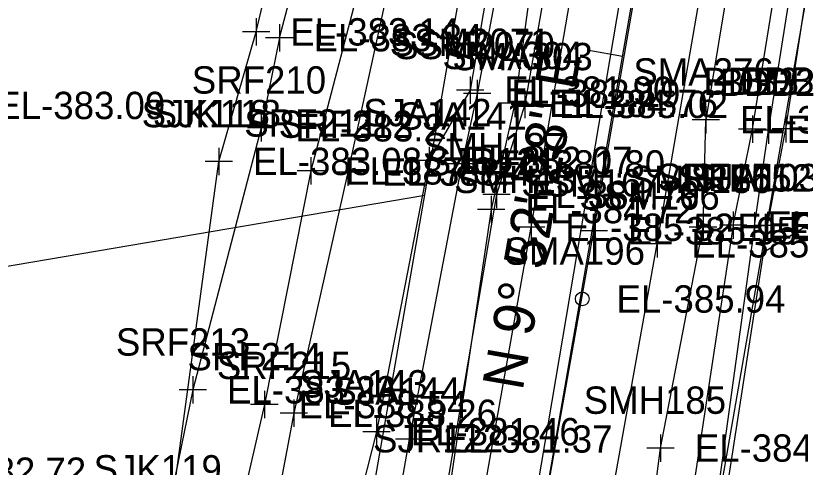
# Model space of a CAD drawing. Extents: x 1189978 to 1314812, y 571533 to 629339.
# Drawn here: x 1217630 to 1217744.7, y 622456.3 to 622522.3 of the extents above; entities that cross this region are included whole.
import ezdxf

# ---------------------------------------------------------------- set-up
doc = ezdxf.new("R2010")
doc.units = 0
for name, color, linetype in [('SURVEY - CENTERLINE - Preliminary', 7, 'Continuous'), ('SURVEY - CENTERLINE - Preliminary Text', 7, 'Continuous'), ('SURVEY - DRAINAGE - Area Shapes', 7, 'Continuous'), ('SURVEY - DTM - Breaklines', 7, 'Continuous'), ('SURVEY - DTM - Breaklines - Points - Elevations', 7, 'Continuous'), ('SURVEY - DTM - Breaklines - Points - Locators', 7, 'Continuous'), ('SURVEY - DTM - Breaklines - Points - Numbers', 7, 'Continuous'), ('SURVEY - DTM - Spot Points - Elevations', 7, 'Continuous'), ('SURVEY - DTM - Spot Points - Locators', 7, 'Continuous'), ('SURVEY - DTM - Spot Points - Point Numbers', 7, 'Continuous'), ('SURVEY - PROPERTY - ROW Lines', 7, 'Continuous'), ('SURVEY - PROPERTY - ROW Lines Text', 7, 'Continuous'), ('SURVEY - TRANSPORTATION - Roads', 7, 'Continuous'), ('SURVEY - TRANSPORTATION - Roads - Points - Elevations', 7, 'Continuous'), ('SURVEY - TRANSPORTATION - Roads - Points - Locators', 7, 'Continuous'), ('SURVEY - TRANSPORTATION - Roads - Points - Numbers', 7, 'Continuous'), ('SURVEY - VEGETATION - Features - Points - Elevations', 7, 'Continuous'), ('SURVEY - VEGETATION - Features - Points - Locators', 7, 'Continuous'), ('SURVEY - VEGETATION - Features - Points - Numbers', 7, 'Continuous'), ('SURVEY - VEGETATION - Features with Text', 7, 'Continuous')]:
    doc.layers.add(name, color=color, linetype=linetype)

msp = doc.modelspace()

# ---------------------------------------------------------------- linework, layer by layer
at = {"layer": 'SURVEY - CENTERLINE - Preliminary'}
msp.add_line((1217671.49, 622245.09), (1217757.38, 622738.49), dxfattribs=at)
msp.add_line((1217671.49, 622245.09), (1217757.38, 622738.49), dxfattribs=at)
at = {"layer": 'SURVEY - CENTERLINE - Preliminary Text'}
msp.add_line((1217718.71, 622516.35), (1217713.78, 622517.2), dxfattribs=at)
at = {"layer": 'SURVEY - DRAINAGE - Area Shapes'}
msp.add_line((1217415.87, 620731.68), (1218149.36, 625079.9), dxfattribs=at)
at = {"layer": 'SURVEY - DTM - Breaklines'}
for points in [[(1217668.55, 622519.09), (1217682.04, 622569.99), (1217692.31, 622624.39), (1217697.1, 622674.13), (1217713.24, 622744.52)], [(1217737.61, 622740.22), (1217730.46, 622698.15), (1217719.61, 622639.27), (1217707.78, 622578.17), (1217696.43, 622511.42)], [(1217739.11, 622740.05), (1217732.14, 622698.06), (1217721.65, 622639.18), (1217710.18, 622578.17), (1217697.46, 622510.95)], [(1217743.69, 622740.07), (1217733.36, 622683.6), (1217725.95, 622634.1), (1217715.94, 622575.63), (1217704.42, 622509.33)], [(1217591.74, 621765.73), (1217601.34, 621822.74), (1217608.84, 621869.52), (1217625.54, 621971.19), (1217634.6, 622026.63), (1217643.17, 622076.74), (1217651.21, 622124.47), (1217659.56, 622173.57), (1217668.17, 622224.78), (1217678.08, 622282.54), (1217688.16, 622340.37), (1217697.26, 622392.62), (1217705.46, 622440.01), (1217714.49, 622490.86), (1217723.28, 622541.33), (1217731.44, 622588.51), (1217739.96, 622637.78), (1217748.52, 622688.04), (1217748.57, 622688.21), (1217756.95, 622738.51)], [(1217769.33, 622736.43), (1217759.55, 622680.57), (1217750.63, 622625.42), (1217740.94, 622568.2), (1217730.86, 622507.08)], [(1217734.86, 622491.68), (1217737.66, 622505.69), (1217746.02, 622557.47), (1217746.36, 622558.29), (1217753.75, 622608.13), (1217762.31, 622662.25), (1217768.52, 622704.08), (1217774.11, 622735.63)], [(1217737.99, 622491.58), (1217740.03, 622505.55), (1217748.3, 622557.84), (1217755.93, 622607.65), (1217764.2, 622662.81), (1217771.05, 622703.98), (1217776.29, 622735.55)], [(1217739.88, 622491.64), (1217742.56, 622505.77), (1217750.42, 622557.52), (1217758.51, 622607.95), (1217767.15, 622662.37), (1217774.48, 622704.32), (1217779.41, 622734.61)], [(1217685.05, 622529.18), (1217678.55, 622499.44), (1217670.66, 622464.16), (1217662, 622418.29), (1217653.65, 622375.31), (1217647.46, 622326.5), (1217637.7, 622278.06), (1217624.97, 622233.51), (1217617.77, 622187.81), (1217609.29, 622147.05), (1217599.66, 622101.36), (1217592.56, 622056.45), (1217583.44, 622007.19), (1217575.28, 621964.22), (1217564.77, 621919.14), (1217554.54, 621865.01), (1217546.46, 621821.67), (1217537.02, 621781.08), (1217528.09, 621784.53), (1217517.71, 621784.08)], [(1217681.03, 622529.83), (1217673.16, 622499.61), (1217666.36, 622465.44), (1217655.82, 622419.52), (1217648.28, 622375.91), (1217643.04, 622327.33), (1217632.09, 622280.16), (1217619.71, 622235.27), (1217613.14, 622189.16), (1217602.51, 622145.75), (1217593.94, 622101.94), (1217587.9, 622057.35), (1217577.79, 622010.33), (1217570.45, 621965.56), (1217560.55, 621920.1), (1217546.67, 621868.08), (1217539.32, 621822.52), (1217534.84, 621801.11)], [(1217668.55, 622519.09), (1217665.88, 622505.91), (1217655.91, 622467.59), (1217646.62, 622422.12), (1217637.66, 622376.33), (1217630.45, 622330.1), (1217619.94, 622285.29), (1217610.06, 622239.5), (1217600.78, 622197.96), (1217592.86, 622149.6), (1217580.28, 622104.6), (1217573.51, 622060.94), (1217562.45, 622014.24), (1217553.23, 621969.79), (1217544.82, 621922.02), (1217535.21, 621868.88), (1217526.29, 621827.9)], [(1217696.43, 622511.42), (1217690.45, 622501.14), (1217682.75, 622461.47), (1217672.56, 622421.42), (1217668.77, 622381.8), (1217659.15, 622328.76), (1217653.09, 622287.28), (1217639.42, 622228.14), (1217631.31, 622175.39), (1217620.6, 622119.17), (1217610.69, 622074.17), (1217604.05, 622032.34), (1217595.02, 621981.54), (1217586.73, 621935.16), (1217578.82, 621892.7), (1217571.48, 621848.7), (1217561.74, 621801.1), (1217546.07, 621743.68), (1217517.89, 621741.61)], [(1217697.46, 622510.95), (1217695.23, 622500.63), (1217687.54, 622460.4), (1217680.36, 622419.79), (1217673.4, 622382.01), (1217663.19, 622329.29), (1217655.83, 622286.39), (1217645.17, 622227.36), (1217637.36, 622175.23), (1217627.75, 622118.91), (1217619.76, 622071.57), (1217612.88, 622029.47), (1217598.58, 621981.08), (1217592.58, 621934.99), (1217582.82, 621892.2), (1217576.26, 621849.18), (1217566.85, 621799.58), (1217549.42, 621742.26), (1217567.14, 621728.67)], [(1217704.42, 622509.33), (1217700.3, 622496.16), (1217691.81, 622446.34), (1217683.59, 622396.11), (1217675.05, 622345.79), (1217666.22, 622294.23), (1217657.54, 622241.9), (1217648.88, 622192.24), (1217640.73, 622142.53), (1217632.56, 622094.35), (1217625.38, 622048.54), (1217615.19, 621995.99), (1217607.27, 621946.79), (1217598.3, 621895.28), (1217589.38, 621843.86), (1217580.22, 621794.45), (1217573.72, 621781.31), (1217574.43, 621774.4), (1217580.6, 621768.52)], [(1217604.56, 621765.51), (1217608.59, 621775.31), (1217618.98, 621822.73), (1217628.13, 621872.31), (1217636.41, 621920.88), (1217646.75, 621970.08), (1217652.31, 622022.79), (1217663.53, 622069.73), (1217672.49, 622118.54), (1217678.26, 622168.97), (1217683.24, 622219.55), (1217691.94, 622272.25), (1217701.2, 622320.93), (1217709.61, 622368.48), (1217718.57, 622415.45), (1217724.25, 622459.08), (1217730.45, 622491.37), (1217730.86, 622507.08)], [(1217734.86, 622491.68), (1217727.91, 622445.78), (1217720.64, 622398.43), (1217714.5, 622352.23), (1217706.13, 622302.11), (1217699.65, 622260.42), (1217693, 622212.18), (1217687.82, 622174.51), (1217684.08, 622136.25), (1217675.85, 622096.46), (1217671.96, 622067.67), (1217669.46, 622048.53), (1217661.22, 621993.63), (1217653.56, 621948.52), (1217646.28, 621917), (1217643.83, 621906.18), (1217644.06, 621905.86), (1217641.41, 621873.35), (1217633.96, 621824.29), (1217625.6, 621785.71), (1217619.08, 621762.41), (1217607.58, 621724.78)], [(1217737.99, 622491.58), (1217731.67, 622445.99), (1217724.08, 622397.71), (1217716.9, 622351.79), (1217709.45, 622301.8), (1217702.84, 622260.49), (1217695.06, 622212.22), (1217690.49, 622174.72), (1217686.87, 622136.14), (1217680.45, 622095.18), (1217675.01, 622067.1), (1217678.26, 622054.48), (1217691.84, 622049.62), (1217699.98, 622049.72)], [(1217739.88, 622491.64), (1217732.77, 622445.6), (1217725.75, 622396.67), (1217718.01, 622351.18), (1217711.55, 622301.06), (1217705.23, 622260.06), (1217697.9, 622211.38), (1217691.93, 622173.62), (1217688.78, 622135.98), (1217683.07, 622094), (1217680.22, 622062.81), (1217683.31, 622059.64), (1217688.49, 622056.78), (1217698.9, 622055.52)]]:
    msp.add_lwpolyline(points, dxfattribs=at)
at = {"layer": 'SURVEY - DTM - Breaklines - Points - Locators'}
for p, q in [((1217668.55, 622521.09), (1217668.55, 622517.09)), ((1217670.55, 622519.09), (1217666.55, 622519.09)), ((1217696.43, 622513.42), (1217696.43, 622509.42)), ((1217697.46, 622512.95), (1217697.46, 622508.95)), ((1217698.43, 622511.42), (1217694.43, 622511.42)), ((1217699.46, 622510.95), (1217695.46, 622510.95)), ((1217704.42, 622511.33), (1217704.42, 622507.33)), ((1217706.42, 622509.33), (1217702.42, 622509.33)), ((1217730.86, 622509.08), (1217730.86, 622505.08)), ((1217665.88, 622507.91), (1217665.88, 622503.91)), ((1217732.86, 622507.08), (1217728.86, 622507.08)), ((1217737.66, 622507.69), (1217737.66, 622503.69)), ((1217740.03, 622507.55), (1217740.03, 622503.55)), ((1217742.56, 622507.77), (1217742.56, 622503.77)), ((1217667.88, 622505.91), (1217663.88, 622505.91)), ((1217739.66, 622505.69), (1217735.66, 622505.69)), ((1217742.03, 622505.55), (1217738.03, 622505.55)), ((1217744.56, 622505.77), (1217740.56, 622505.77)), ((1217690.45, 622503.14), (1217690.45, 622499.14)), ((1217695.23, 622502.63), (1217695.23, 622498.63)), ((1217673.16, 622501.61), (1217673.16, 622497.61)), ((1217678.55, 622501.44), (1217678.55, 622497.44)), ((1217692.45, 622501.14), (1217688.45, 622501.14)), ((1217697.23, 622500.63), (1217693.23, 622500.63)), ((1217675.16, 622499.61), (1217671.16, 622499.61)), ((1217680.55, 622499.44), (1217676.55, 622499.44)), ((1217700.3, 622498.16), (1217700.3, 622494.16)), ((1217702.3, 622496.16), (1217698.3, 622496.16)), ((1217730.45, 622493.37), (1217730.45, 622489.37)), ((1217734.86, 622493.68), (1217734.86, 622489.68)), ((1217737.99, 622493.58), (1217737.99, 622489.58)), ((1217739.88, 622493.64), (1217739.88, 622489.64)), ((1217714.49, 622492.86), (1217714.49, 622488.86)), ((1217732.45, 622491.37), (1217728.45, 622491.37)), ((1217736.86, 622491.68), (1217732.86, 622491.68)), ((1217739.99, 622491.58), (1217735.99, 622491.58)), ((1217741.88, 622491.64), (1217737.88, 622491.64)), ((1217716.49, 622490.86), (1217712.49, 622490.86)), ((1217655.91, 622469.59), (1217655.91, 622465.59)), ((1217657.91, 622467.59), (1217653.91, 622467.59)), ((1217666.36, 622467.44), (1217666.36, 622463.44)), ((1217670.66, 622466.16), (1217670.66, 622462.16)), ((1217668.36, 622465.44), (1217664.36, 622465.44)), ((1217672.66, 622464.16), (1217668.66, 622464.16)), ((1217682.75, 622463.47), (1217682.75, 622459.47)), ((1217687.54, 622462.4), (1217687.54, 622458.4)), ((1217684.75, 622461.47), (1217680.75, 622461.47)), ((1217689.54, 622460.4), (1217685.54, 622460.4)), ((1217724.25, 622461.08), (1217724.25, 622457.08)), ((1217726.25, 622459.08), (1217722.25, 622459.08))]:
    msp.add_line(p, q, dxfattribs=at)
at = {"layer": 'SURVEY - DTM - Spot Points - Locators'}
msp.add_circle((1217712.81, 622480.88), 1, dxfattribs=at)
at = {"layer": 'SURVEY - PROPERTY - ROW Lines'}
for p, q in [((1217646.86, 622249.38), (1217732.74, 622742.76)), ((1217696.12, 622240.81), (1217782.01, 622734.2))]:
    msp.add_line(p, q, dxfattribs=at)
at = {"layer": 'SURVEY - PROPERTY - ROW Lines Text'}
for points in [[(1217785.97, 622516.35), (1217739.06, 622487.51)], [(1217620.45, 622484.24), (1217689.8, 622496.07)]]:
    msp.add_lwpolyline(points, dxfattribs=at)
at = {"layer": 'SURVEY - TRANSPORTATION - Roads'}
for points in [[(1217582.48, 621767.23), (1217583.27, 621767.61), (1217591.48, 621818.57), (1217599.69, 621870.76), (1217607.53, 621920.91), (1217615.95, 621971.91), (1217624.34, 622024.82), (1217633.57, 622076.49), (1217641.88, 622125.54), (1217650.64, 622175.68), (1217659.24, 622225.33), (1217669.03, 622282.56), (1217679.25, 622341.35), (1217687.87, 622391.11), (1217696.47, 622441.53), (1217705.33, 622491.37), (1217713.95, 622541.79), (1217722.13, 622587.98), (1217731.03, 622638.52), (1217739.75, 622690.1), (1217739.95, 622691.24)], [(1217602.44, 621764.03), (1217601.61, 621764.4), (1217609.73, 621817.52), (1217617.85, 621867.88), (1217626.38, 621920.56), (1217634.53, 621969.83), (1217643.58, 622024.64), (1217652.44, 622075.54), (1217660.7, 622123.44), (1217668.82, 622172.59), (1217677.49, 622224.09), (1217697.4, 622338.83), (1217706.31, 622389.43), (1217714.67, 622438.11), (1217723.73, 622488.94), (1217732.47, 622539.47), (1217740.61, 622586), (1217749.34, 622636.23), (1217757.51, 622686.56)]]:
    msp.add_lwpolyline(points, dxfattribs=at)
at = {"layer": 'SURVEY - TRANSPORTATION - Roads - Points - Locators'}
for p, q in [((1217705.33, 622493.37), (1217705.33, 622489.37)), ((1217707.33, 622491.37), (1217703.33, 622491.37)), ((1217723.73, 622490.94), (1217723.73, 622486.94)), ((1217725.73, 622488.94), (1217721.73, 622488.94))]:
    msp.add_line(p, q, dxfattribs=at)
at = {"layer": 'SURVEY - VEGETATION - Features - Points - Locators'}
for p, q in [((1217665.15, 622521.94), (1217665.15, 622517.94)), ((1217667.15, 622519.94), (1217663.15, 622519.94)), ((1217702.96, 622511.49), (1217702.96, 622507.49)), ((1217704.96, 622509.49), (1217700.96, 622509.49)), ((1217659.71, 622502.99), (1217659.71, 622498.99)), ((1217659.71, 622502.99), (1217659.71, 622498.99)), ((1217661.71, 622500.99), (1217657.71, 622500.99)), ((1217661.71, 622500.99), (1217657.71, 622500.99)), ((1217699.51, 622495.95), (1217699.51, 622491.95)), ((1217701.51, 622493.95), (1217697.51, 622493.95))]:
    msp.add_line(p, q, dxfattribs=at)
at = {"layer": 'SURVEY - VEGETATION - Features with Text'}
for points in [[(1217665.15, 622519.94), (1217677.28, 622571.02), (1217691.69, 622624.61), (1217692.41, 622674.92), (1217699.29, 622743.11)], [(1217740.63, 622740.74), (1217724.82, 622684.22), (1217725, 622633.65), (1217712.02, 622576.45), (1217702.96, 622509.49)], [(1217575.08, 621774.11), (1217450.26, 621814.85), (1217450.11, 621824.86), (1217507.38, 621858.46), (1217523.69, 621881.47), (1217539.67, 621940.19), (1217555.11, 622005.06), (1217569.39, 622072.91), (1217588.39, 622140.3), (1217598.23, 622184.22), (1217608.56, 622234.27), (1217619.43, 622285.83), (1217630.65, 622335.58), (1217641.81, 622391.46), (1217652.67, 622449.04), (1217659.71, 622500.99), (1217665.15, 622519.94)], [(1217702.96, 622509.49), (1217699.51, 622493.95), (1217693.48, 622453.44), (1217687.22, 622414.99), (1217679.9, 622375.82), (1217673.76, 622340.63), (1217665.91, 622295.21), (1217658.91, 622253.42), (1217654.9, 622206.36), (1217645.64, 622163.87), (1217637.41, 622119.23), (1217630.2, 622079.47), (1217625.49, 622037.7), (1217617.96, 622003.15), (1217610.75, 621959.64), (1217601.11, 621912.04), (1217596.35, 621872.4), (1217583.12, 621827.95), (1217575.08, 621774.11)]]:
    msp.add_lwpolyline(points, dxfattribs=at)

# ---------------------------------------------------------------- texts
at = {"layer": 'SURVEY - CENTERLINE - Preliminary Text'}
msp.add_text('N 9%%d 52\' 28" E', height=6, rotation=80.1256, dxfattribs=at).set_placement((1217704.09, 622467.33))
at = {"layer": 'SURVEY - DTM - Breaklines - Points - Elevations'}
for s, p in [('EL-383.34', (1217673.55, 622517.09)), ('EL-381.90', (1217701.43, 622509.42)), ('EL-382.19', (1217702.46, 622508.95)), ('EL-385.02', (1217709.42, 622507.33)), ('EL-384.96', (1217735.86, 622505.08)), ('EL-383.21', (1217670.88, 622503.91)), ('EL-383.28', (1217742.66, 622503.69)), ('EL-382.07', (1217695.45, 622499.14)), ('EL-381.80', (1217700.23, 622498.63)), ('EL-387.92', (1217678.16, 622497.61)), ('EL-388.42', (1217683.55, 622497.44)), ('EL-384.79', (1217705.3, 622494.16)), ('EL-384.69', (1217735.45, 622489.37)), ('EL-383.21', (1217739.86, 622489.68)), ('EL-383.12', (1217742.99, 622489.58)), ('EL-385.95', (1217719.49, 622488.86)), ('EL-383.23', (1217660.91, 622465.59)), ('EL-388.54', (1217671.36, 622463.44)), ('EL-388.26', (1217675.66, 622462.16)), ('EL-381.46', (1217687.75, 622459.47)), ('EL-381.37', (1217692.54, 622458.4)), ('EL-384.71', (1217729.25, 622457.08))]:
    msp.add_text(s, height=4, dxfattribs=at).set_placement(p)
at = {"layer": 'SURVEY - DTM - Breaklines - Points - Numbers'}
for s, p in [('SSM2071', (1217684.67, 622516.42)), ('SSM2070', (1217685.33, 622515.95)), ('SMA303', (1217693.83, 622514.33)), ('SMA276', (1217720.27, 622512.08)), ('SRF210', (1217655.76, 622510.91)), ('BDB3', (1217730.49, 622510.69)), ('BDB2', (1217732.88, 622510.55)), ('BDB1', (1217735.78, 622510.77)), ('SJA142', (1217680.81, 622506.14)), ('SJA141', (1217685.96, 622505.63)), ('SRF211', (1217663.43, 622504.61)), ('SRF212', (1217668.45, 622504.44)), ('SMH187', (1217689.55, 622501.16)), ('SMH186', (1217719.7, 622496.37)), ('SRF151', (1217723.77, 622496.68)), ('SRF152', (1217726.75, 622496.58)), ('SJA103', (1217728.64, 622496.64)), ('SSM167', (1217703.9, 622495.86)), ('SRF213', (1217644.67, 622472.59)), ('SRF214', (1217655.13, 622470.44)), ('SRF215', (1217659.42, 622469.16)), ('SJA143', (1217671.51, 622466.47)), ('SJA144', (1217676.3, 622465.4)), ('SMH185', (1217713.01, 622464.08))]:
    msp.add_text(s, height=4, dxfattribs=at).set_placement(p)
at = {"layer": 'SURVEY - DTM - Spot Points - Elevations'}
for s, p in [('EL-383.09', (1217627.2, 622507.18)), ('EL-385.94', (1217717.81, 622478.88)), ('EL-382.72', (1217615.64, 622453.69))]:
    msp.add_text(s, height=4, dxfattribs=at).set_placement(p)
at = {"layer": 'SURVEY - DTM - Spot Points - Point Numbers'}
msp.add_text('SMA196', height=4, dxfattribs=at).set_placement((1217701.46, 622485.88))
at = {"layer": 'SURVEY - TRANSPORTATION - Roads - Points - Elevations'}
for s, p in [('EL-385.52', (1217710.33, 622489.37)), ('EL-385.43', (1217728.73, 622486.94))]:
    msp.add_text(s, height=4, dxfattribs=at).set_placement(p)
at = {"layer": 'SURVEY - TRANSPORTATION - Roads - Points - Numbers'}
for s, p in [('SMH135', (1217694.09, 622496.37)), ('SSM166', (1217712.38, 622493.94))]:
    msp.add_text(s, height=4, dxfattribs=at).set_placement(p)
at = {"layer": 'SURVEY - VEGETATION - Features - Points - Elevations'}
for s, p in [('EL-383.14', (1217670.15, 622517.94)), ('EL-384.76', (1217707.96, 622507.49)), ('EL-383.08', (1217664.71, 622498.99)), ('EL-383.08', (1217664.71, 622498.99)), ('EL-384.72', (1217704.51, 622491.95))]:
    msp.add_text(s, height=4, dxfattribs=at).set_placement(p)
at = {"layer": 'SURVEY - VEGETATION - Features - Points - Numbers'}
for s, p in [('SMA304', (1217692.38, 622514.49)), ('SJK118', (1217648.43, 622505.99)), ('SJK118', (1217650.05, 622505.99)), ('SJR121', (1217690.09, 622498.95)), ('SJR122', (1217682.24, 622458.44)), ('SJK119', (1217641.41, 622454.04))]:
    msp.add_text(s, height=4, dxfattribs=at).set_placement(p)

doc.saveas('drawing.dxf')
